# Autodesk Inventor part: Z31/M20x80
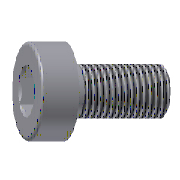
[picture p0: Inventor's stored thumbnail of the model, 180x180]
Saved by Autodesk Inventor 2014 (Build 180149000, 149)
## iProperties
Created: 2009-11
Part Number: Z31/M20x80
Material: Steel, Mild
Description: Hexagon Socket Head Cap Screw
Document SubType Name: Modeling
Designer: gaom
Standard Revision: 1
Manufacturer: HASCO
Language: en-US
Size Designation: M20x80
Categories: <MemberInstance><Categories><Category DisplayName="Mold" InternalName="349578f2-f4d4-4954-8c09-8e99297a61c0" Mnemonic="MOLD"><Category DisplayName="Fasteners" I
Mass: 0.133121 g
Surface Area: 2.01441 cm^2
Volume: 0.133121 cm^3
Density: 7.86 g/cm^3
Appearance: Steel
IsCustomPart: 0
Author: gaom
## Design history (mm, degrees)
body "Solid1"
revolve "Revolution1" stored, may be unused: angle "d44" = 90 deg
sketch "Sketch2"
  geometry: L1 (0, 9.815)-(8.5, 4.907); L2 (8.5, 4.907)-(8.5, -4.907); L3 (8.5, -4.907)-(0, -9.815); L4 (0, -9.815)-(-8.5, -4.907); L5 (-8.5, -4.907)-(-8.5, 4.907); L6 (-8.5, 4.907)-(0, 9.815); 3 further points
  constraints: 12 end point, 2 vertical alignment, 1 coincident, 14 other
extrude "Extrusion1" cut sketch "Sketch2" taper "d9" = 0 deg; stored distance "d45" = 10
thread "Thread1" dims "d10" = 52 (= b), "d11" = 0
chamfer "Chamfer1" distance "d12" = 1.25 (= 0.5 x P); stored, may be unused: second distance "d50" = 2, angle "d51" = 45 deg
fillet "Fillet1" dims "d13" = 1.25 (= 0.5 x P)
sketch "Sketch1"
  geometry: L1 (0, -100)-(0, 40) reference; L2 (9.815, 20)-(15, 20); L3 (15, 20)-(15, 0); L4 (15, 0)-(10, 0); L5 (10, 0)-(10, -80); L6 (10, -80)-(0, -80); L7 (0, 4.893)-(0, -80); L8 (0, 4.893)-(8.5, 10); L9 (8.5, 10)-(8.5, 18.685); L10 (8.5, 18.685)-(9.815, 20); 1 further point
  constraints: 18 end point, 4 vertical, 3 horizontal, 2 point on line
  dimensions: "d0" = 30 diameter of L3 L1 (= dk); "d1" = 20 distance between parallel lines of L4 L2 (= k); "d2" = 20 diameter of L5 L1 (= d); "d3" = 80 distance between parallel lines of L6 L4 (= L); "d4" = 59 deg angle of L1 L8; "d5" = 45 deg angle of L1 L10; "d6" = 17 diameter of L9 L1 (= sw); "d7" = 19.62991 diameter of L2.start L1 (= 1.1547 x sw); "d8" = 10 distance from line of L8.end L2 (= t)
other parameters: "d" = 20 [user parameter; used in 1 equation term], "L" = 80 [user parameter; used in 1 equation term], "dk" = 30 [user parameter; used in 1 equation term], "b" = 52 [user parameter; used in 1 equation term], "k" = 20 [user parameter; used in 1 equation term], "sw" = 17 [user parameter; used in 2 equation terms], "t" = 10 [user parameter; used in 1 equation term], "P" = 2.5 [user parameter; used in 2 equation terms], "d14" = 0, "d15" = 0, "d55" = 0
